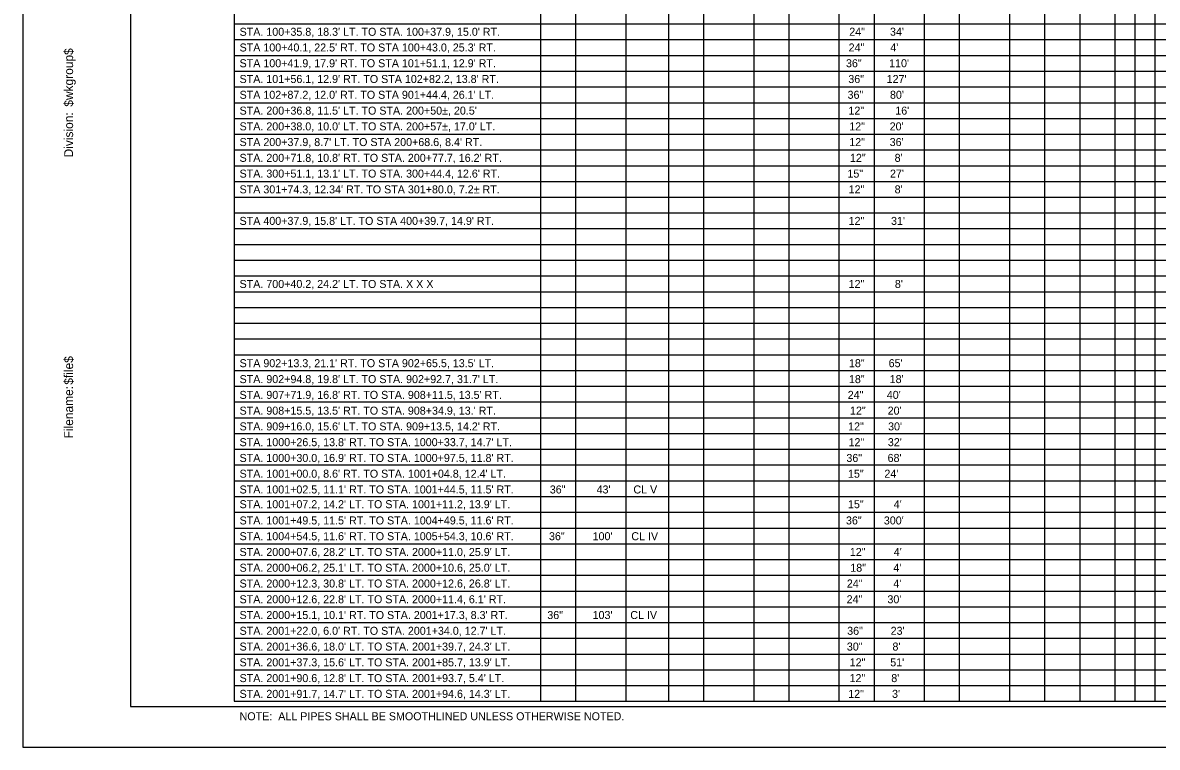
# Model space of a CAD drawing. Extents: x -0.13 to 2.7, y -0.05 to 1.78.
# Drawn here: x -0.135 to 1.283, y -0.051 to 0.854 of the extents above; entities that cross this region are included whole.
import ezdxf

# ---------------------------------------------------------------- set-up
doc = ezdxf.new("R2010")
doc.units = 0
for name, color, linetype in [('ANNOTATION', 7, 'Continuous'), ('BORDER', 7, 'Continuous'), ('PLOT BOUNDARY', 7, 'Continuous')]:
    doc.layers.add(name, color=color, linetype=linetype)

msp = doc.modelspace()

# ---------------------------------------------------------------- linework, layer by layer
at = {"layer": 'BORDER'}
for p, q in [((0, 1.75), (0, 0)), ((0.512, 1.5616), (0.512, 0.0065)), ((0.5559, 1.5616), (0.5559, 0.0065)), ((0.6186, 1.5616), (0.6186, 0.0065)), ((0.6719, 1.5616), (0.6719, 0.0065)), ((0.7158, 1.5616), (0.7158, 0.0065)), ((0.7785, 1.5616), (0.7785, 0.0065)), ((0.8223, 1.5616), (0.8223, 0.0065)), ((0.885, 1.5616), (0.885, 0.0065)), ((0.9289, 1.5616), (0.9289, 0.0065)), ((0.9916, 1.5616), (0.9916, 0.0065)), ((1.0354, 1.5616), (1.0354, 0.0065)), ((1.0982, 1.5616), (1.0982, 0.0065)), ((1.142, 1.5616), (1.142, 0.0065)), ((1.1858, 1.5616), (1.1858, 0.0065)), ((1.2298, 1.5616), (1.2298, 0.0065)), ((1.2548, 1.5616), (1.2548, 0.0065)), ((1.2798, 1.5616), (1.2798, 0.0065)), ((0.1293, 0.853), (2.3707, 0.853)), ((0.1293, 0.8333), (2.3707, 0.8333)), ((0.1293, 0.8136), (2.3707, 0.8136)), ((0.1293, 0.7939), (2.3707, 0.7939)), ((0.1293, 0.7742), (2.3707, 0.7742)), ((0.1293, 0.7545), (2.3707, 0.7545)), ((0.1293, 0.7349), (2.3707, 0.7349)), ((0.1293, 0.7152), (2.3707, 0.7152)), ((0.1293, 0.6955), (2.3707, 0.6955)), ((0.1293, 0.6758), (2.3707, 0.6758)), ((0.1293, 0.6561), (2.3707, 0.6561)), ((0.1293, 0.6364), (2.3707, 0.6364)), ((0.1293, 0.6167), (2.3707, 0.6167)), ((0.1293, 0.5971), (2.3707, 0.5971)), ((0.1293, 0.5774), (2.3707, 0.5774)), ((0.1293, 0.5577), (2.3707, 0.5577)), ((0.1293, 0.538), (2.3707, 0.538)), ((0.1293, 0.5183), (2.3707, 0.5183)), ((0.1293, 0.4986), (2.3707, 0.4986)), ((0.1293, 0.479), (2.3707, 0.479)), ((0.1293, 0.4593), (2.3707, 0.4593)), ((0.1293, 0.4396), (2.3707, 0.4396)), ((0.1293, 0.4199), (2.3707, 0.4199)), ((0.1293, 0.4002), (2.3707, 0.4002)), ((0.1293, 0.3805), (2.3707, 0.3805)), ((0.1293, 0.3608), (2.3707, 0.3608)), ((0.1293, 0.3412), (2.3707, 0.3412)), ((0.1293, 0.3215), (2.3707, 0.3215)), ((0.1293, 0.3018), (2.3707, 0.3018)), ((0.1293, 0.2821), (2.3707, 0.2821)), ((0.1293, 0.2624), (2.3707, 0.2624)), ((0.1293, 0.2427), (2.3707, 0.2427)), ((0.1293, 0.223), (2.3707, 0.223)), ((0.1293, 0.2034), (2.3707, 0.2034)), ((0.1293, 0.1837), (2.3707, 0.1837)), ((0.1293, 0.164), (2.3707, 0.164)), ((0.1293, 0.1443), (2.3707, 0.1443)), ((0.1293, 0.1246), (2.3707, 0.1246)), ((0.1293, 0.1049), (2.3707, 0.1049)), ((0.1293, 0.0853), (2.3707, 0.0853)), ((0.1293, 0.0656), (2.3707, 0.0656)), ((0.1293, 0.0459), (2.3707, 0.0459)), ((0.1293, 0.0262), (2.3707, 0.0262)), ((0, 0), (2.6667, 0)), ((0.1293, 0.0065), (2.3707, 0.0065))]:
    msp.add_line(p, q, dxfattribs=at)
msp.add_lwpolyline([(0.1293, 1.5616), (0.1293, 0.0065), (2.3707, 0.0065), (2.3707, 1.5616)], dxfattribs=at)
at = {"layer": 'PLOT BOUNDARY'}
msp.add_lwpolyline([(-0.1349, -0.051), (2.6984, -0.051), (2.6984, 1.7823), (-0.1349, 1.7823)], close=True, dxfattribs=at)

# ---------------------------------------------------------------- texts
at = {"layer": 'ANNOTATION'}
for s, p in [("STA. 100+35.8, 18.3' LT. TO STA. 100+37.9, 15.0' RT.", (0.1361, 0.8381)), ('24"', (0.8979, 0.8382)), ("34'", (0.9488, 0.8382)), ("STA 100+40.1, 22.5' RT. TO STA 100+43.0, 25.3' RT.", (0.1361, 0.8185)), ('24"', (0.8971, 0.8185)), ("4'", (0.9492, 0.8185)), ("STA 100+41.9, 17.9' RT. TO STA 101+51.1, 12.9' RT.", (0.1361, 0.7988)), ('36"', (0.8938, 0.7988)), ("110'", (0.9477, 0.7988)), ("STA. 101+56.1, 12.9' RT. TO STA 102+82.2, 13.8' RT.", (0.1361, 0.7791)), ('36"', (0.8967, 0.7791)), ("127'", (0.9446, 0.7791)), ("STA 102+87.2, 12.0' RT. TO STA 901+44.4, 26.1' LT.", (0.1361, 0.7594)), ('36"', (0.8958, 0.7594)), ("80'", (0.9488, 0.7594)), ("STA. 200+36.8, 11.5' LT. TO STA. 200+50%%p, 20.5' ", (0.1361, 0.7396)), ('12"', (0.8969, 0.7396)), ("16'", (0.9554, 0.7396)), ("STA. 200+38.0, 10.0' LT. TO STA. 200+57%%p, 17.0' LT.", (0.1361, 0.7199)), ('12" ', (0.8979, 0.7199)), ("20'", (0.9484, 0.7199)), ("STA 200+37.9, 8.7' LT. TO STA 200+68.6, 8.4' RT.", (0.1361, 0.7003)), ('12" ', (0.8979, 0.7003)), ("36'", (0.9484, 0.7003)), ("STA. 200+71.8, 10.8' RT. TO STA. 200+77.7, 16.2' RT.", (0.1361, 0.6806)), ('12" ', (0.8988, 0.6806)), ("8'", (0.9546, 0.6806)), ("STA. 300+51.1, 13.1' LT. TO STA. 300+44.4, 12.6' RT.", (0.1361, 0.6609)), ('15"', (0.8956, 0.6609)), ("27'", (0.9488, 0.6609)), ("STA 301+74.3, 12.34' RT. TO STA 301+80.0, 7.2%%p RT.", (0.1361, 0.6412)), ('12" ', (0.8971, 0.6412)), ("8'", (0.9546, 0.6412)), ("STA 400+37.9, 15.8' LT. TO STA 400+39.7, 14.9' RT.", (0.1361, 0.6018)), ('12" ', (0.8971, 0.6018)), ("31'", (0.9501, 0.6018)), ("STA. 700+40.2, 24.2' LT. TO STA. X X X", (0.1361, 0.523)), ('12" ', (0.8971, 0.523)), ("8'", (0.9549, 0.523)), ("STA 902+13.3, 21.1' RT. TO STA 902+65.5, 13.5' LT.", (0.1361, 0.424)), ('18"', (0.8975, 0.424)), ("65'", (0.9471, 0.424)), ("STA. 902+94.8, 19.8' LT. TO STA. 902+92.7, 31.7' LT.", (0.1361, 0.4041)), ('18"', (0.8975, 0.4041)), ("18'", (0.9484, 0.4041)), ("STA. 907+71.9, 16.8' RT. TO STA. 908+11.5, 13.5' RT.", (0.1361, 0.3844)), ('24"', (0.896, 0.3844)), ("40'", (0.9448, 0.3844)), ("STA. 908+15.5, 13.5' RT. TO STA. 908+34.9, 13.' RT.", (0.1361, 0.3647)), ('12" ', (0.8988, 0.3647)), ("20'", (0.9459, 0.3647)), ("STA. 909+16.0, 15.6' LT. TO STA. 909+13.5, 14.2' RT.", (0.1361, 0.345)), ('12" ', (0.8965, 0.345)), ("30'", (0.9464, 0.345)), ("STA. 1000+26.5, 13.8' RT. TO STA. 1000+33.7, 14.7' LT.", (0.1361, 0.3253)), ('12" ', (0.897, 0.3253)), ("32'", (0.9461, 0.3253)), ("STA. 1000+30.0, 16.9' RT. TO STA. 1000+97.5, 11.8' RT.", (0.1361, 0.3056)), ('36"', (0.8943, 0.3056)), ("68'", (0.9458, 0.3056)), ("STA. 1001+00.0, 8.6' RT. TO STA. 1001+04.8, 12.4' LT.", (0.1361, 0.2859)), ('15"', (0.8963, 0.2859)), ("24'", (0.9418, 0.2859)), ("STA. 1001+02.5, 11.1' RT. TO STA. 1001+44.5, 11.5' RT.", (0.1361, 0.2662)), ('36"', (0.5237, 0.2662)), ("43'", (0.5822, 0.2662)), ('CL V', (0.6282, 0.2662)), ("STA. 1001+07.2, 14.2' LT. TO STA. 1001+11.2, 13.9' LT.", (0.1361, 0.2478)), ('15"', (0.8963, 0.2478)), ("4'", (0.9535, 0.2478)), ("STA. 1001+49.5, 11.5' RT. TO STA. 1004+49.5, 11.6' RT.", (0.1361, 0.2275)), ('36"', (0.8938, 0.2275)), ("300'", (0.9411, 0.2275)), ("STA. 1004+54.5, 11.6' RT. TO STA. 1005+54.3, 10.6' RT.", (0.1361, 0.2078)), ('36"', (0.5227, 0.2078)), ("100'", (0.5772, 0.2078)), ('CL IV', (0.6256, 0.2078)), ("STA. 2000+07.6, 28.2' LT. TO STA. 2000+11.0, 25.9' LT.", (0.1361, 0.1881)), ('12" ', (0.8986, 0.1881)), ("4'", (0.9535, 0.1881)), ("STA. 2000+06.2, 25.1' LT. TO STA. 2000+10.6, 25.0' LT.", (0.1361, 0.1684)), ('18"', (0.8992, 0.1684)), ("4'", (0.953, 0.1684)), ("STA. 2000+12.3, 30.8' LT. TO STA. 2000+12.6, 26.8' LT.", (0.1361, 0.1487)), ('24"', (0.8949, 0.1487)), ("4'", (0.953, 0.1487)), ("STA. 2000+12.6, 22.8' LT. TO STA. 2000+11.4, 6.1' RT.", (0.1361, 0.129)), ('24"', (0.8946, 0.129)), ("30'", (0.9456, 0.129)), ("STA. 2000+15.1, 10.1' RT. TO STA. 2001+17.3, 8.3' RT.", (0.1361, 0.1093)), ('36"', (0.5206, 0.1093)), ("103'", (0.5772, 0.1093)), ('CL IV', (0.6243, 0.1093)), ("STA. 2001+22.0, 6.0' RT. TO STA. 2001+34.0, 12.7' LT.", (0.1361, 0.0896)), ('36"', (0.8953, 0.0896)), ("23'", (0.9496, 0.0896)), ("STA. 2001+36.6, 18.0' LT. TO STA. 2001+39.7, 24.3' LT.", (0.1361, 0.0699)), ('30"', (0.8949, 0.0699)), ("8'", (0.9519, 0.0699)), ("STA. 2001+37.3, 15.6' LT. TO STA. 2001+85.7, 13.9' LT.", (0.1361, 0.0502)), ('12" ', (0.8984, 0.0502)), ("51'", (0.9491, 0.0502)), ("STA. 2001+90.6, 12.8' LT. TO STA. 2001+93.7, 5.4' LT.", (0.1361, 0.0305)), ('12" ', (0.8983, 0.0305)), ("8'", (0.9504, 0.0305)), ("STA. 2001+91.7, 14.7' LT. TO STA. 2001+94.6, 14.3' LT.", (0.1361, 0.0108)), ('12" ', (0.8966, 0.0108)), ("3'", (0.9514, 0.0108)), ('NOTE:  ALL PIPES SHALL BE SMOOTHLINED UNLESS OTHERWISE NOTED.', (0.1361, -0.0172))]:
    msp.add_text(s, height=0.01, dxfattribs=at).set_placement(p)
at = {"layer": 'BORDER'}
for s, p in [('$wkgroup$', (-0.0719, 0.7495)), ('Division:', (-0.0719, 0.6861)), ('$file$', (-0.0719, 0.4021)), ('Filename:', (-0.0719, 0.335))]:
    msp.add_text(s, height=0.01116, rotation=90, dxfattribs=at).set_placement(p)

doc.saveas('drawing.dxf')
